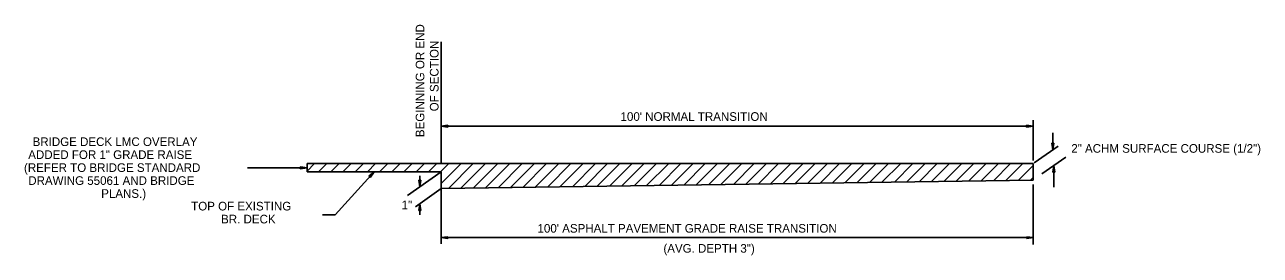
# Model space of a CAD drawing. Extents: x 1931522 to 1935523, y 600380 to 605075.
# Drawn here: x 1931534 to 1932393, y 602766 to 602926 of the extents above; entities that cross this region are included whole.
import ezdxf

# ---------------------------------------------------------------- set-up
doc = ezdxf.new("R2010")
doc.units = 0
doc.layers.add('Default', color=7, linetype='Continuous')
doc.layers.add('R_Border', color=7, linetype='Continuous')

msp = doc.modelspace()

# ---------------------------------------------------------------- linework, layer by layer
at = {"layer": 'Default'}
for p, q in [((1931823.87, 602829.84), (1931823.87, 602914.36)), ((1932235.2, 602831.98), (1932235.2, 602859.98)), ((1931828.54, 602856.49), (1931823.87, 602855.83)), ((1931823.87, 602855.83), (1932235.2, 602855.83)), ((1931828.54, 602855.16), (1931823.87, 602855.83)), ((1931828.54, 602856.27), (1931824.55, 602855.83)), ((1931828.54, 602855.16), (1931824.55, 602855.83)), ((1931828.54, 602856.27), (1931825.44, 602855.83)), ((1931828.54, 602855.38), (1931825.44, 602855.83)), ((1931828.54, 602856.05), (1931826.33, 602855.83)), ((1931828.54, 602855.38), (1931826.33, 602855.83)), ((1931828.54, 602856.05), (1931826.99, 602855.83)), ((1931828.54, 602855.61), (1931826.99, 602855.83)), ((1931828.54, 602855.83), (1931827.88, 602855.83)), ((1931828.54, 602855.61), (1931827.88, 602855.83)), ((1931828.54, 602855.16), (1931828.54, 602856.49)), ((1932230.53, 602856.49), (1932235.2, 602855.83)), ((1932230.53, 602856.49), (1932230.53, 602855.16)), ((1932230.53, 602856.27), (1932233.65, 602855.83)), ((1932230.53, 602856.27), (1932234.3, 602855.83)), ((1932230.53, 602856.05), (1932232.08, 602855.83)), ((1932230.53, 602856.05), (1932232.76, 602855.83)), ((1932230.53, 602855.16), (1932235.2, 602855.83)), ((1932230.53, 602855.61), (1932232.08, 602855.83)), ((1932230.53, 602855.38), (1932233.65, 602855.83)), ((1932230.53, 602855.16), (1932234.3, 602855.83)), ((1932230.53, 602855.38), (1932232.76, 602855.83)), ((1932230.53, 602855.61), (1932231.2, 602855.83)), ((1932230.53, 602855.83), (1932231.2, 602855.83)), ((1932248.96, 602839.41), (1932248.96, 602851.18)), ((1932235.88, 602830.35), (1932252.52, 602841.86)), ((1932248.3, 602844.08), (1932248.96, 602839.41)), ((1932249.63, 602844.08), (1932248.3, 602844.08)), ((1932248.53, 602844.08), (1932248.96, 602840.97)), ((1932248.53, 602844.08), (1932248.96, 602840.31)), ((1932248.74, 602844.08), (1932248.96, 602842.53)), ((1932248.74, 602844.08), (1932248.96, 602841.86)), ((1932249.63, 602844.08), (1932248.96, 602839.41)), ((1932249.18, 602844.08), (1932248.96, 602842.53)), ((1932249.42, 602844.08), (1932248.96, 602840.97)), ((1932249.63, 602844.08), (1932248.96, 602840.31)), ((1932249.42, 602844.08), (1932248.96, 602841.86)), ((1932248.96, 602844.08), (1932248.96, 602843.41)), ((1932249.18, 602844.08), (1932248.96, 602843.41)), ((1932241.31, 602822.65), (1932257.84, 602834.31)), ((1931689.17, 602826.79), (1931730.62, 602826.95)), ((1931725.91, 602826.22), (1931725.96, 602827.63)), ((1931725.91, 602826.22), (1931730.62, 602826.95)), ((1931725.92, 602827.33), (1931729.03, 602826.88)), ((1931725.96, 602827.63), (1931730.62, 602826.95)), ((1931725.96, 602826.53), (1931727.61, 602826.92)), ((1931725.96, 602826.53), (1931728.22, 602826.83)), ((1931726.01, 602826.84), (1931726.8, 602826.89)), ((1931726.01, 602826.84), (1931726.8, 602826.89)), ((1931726.05, 602827.15), (1931727.61, 602826.92)), ((1931726.05, 602827.15), (1931728.22, 602826.83)), ((1931726.09, 602827.46), (1931729.83, 602826.91)), ((1931726.09, 602826.36), (1931729.83, 602826.91)), ((1931726.09, 602826.36), (1931729.03, 602826.88)), ((1931730.62, 602824.06), (1931823.87, 602824.07)), ((1931750.04, 602794.26), (1931777.25, 602824.07)), ((1931773.59, 602821.1), (1931777.25, 602824.07)), ((1931773.78, 602820.86), (1931776.22, 602822.84)), ((1931773.8, 602821.08), (1931776.74, 602823.46)), ((1931774.59, 602820.11), (1931777.25, 602824.07)), ((1931774.61, 602820.33), (1931776.74, 602823.46)), ((1931774.61, 602820.33), (1931776.22, 602822.84)), ((1931800.32, 602807.77), (1931823.87, 602824.07)), ((1931823.87, 602774.21), (1931823.87, 602824.07)), ((1932248.92, 602823.81), (1932249.58, 602828.48)), ((1932248.92, 602823.81), (1932250.25, 602823.81)), ((1932249.14, 602823.81), (1932249.58, 602827.81)), ((1932249.14, 602823.81), (1932249.58, 602826.91)), ((1932249.35, 602823.81), (1932249.58, 602826.25)), ((1932249.35, 602823.81), (1932249.58, 602825.35)), ((1932249.58, 602813.37), (1932249.58, 602828.48)), ((1932250.25, 602823.81), (1932249.58, 602828.48)), ((1932250.25, 602823.81), (1932249.58, 602827.81)), ((1932250.03, 602823.81), (1932249.58, 602826.91)), ((1932250.03, 602823.81), (1932249.58, 602826.25)), ((1932249.8, 602823.81), (1932249.58, 602825.35)), ((1932249.8, 602823.81), (1932249.58, 602824.7)), ((1932249.58, 602823.81), (1932249.58, 602824.7)), ((1931774.59, 602820.11), (1931773.59, 602821.1)), ((1931774.01, 602820.84), (1931775.7, 602822.21)), ((1931774.01, 602820.84), (1931775.23, 602821.83)), ((1931774.21, 602820.6), (1931774.7, 602821.21)), ((1931774.21, 602820.6), (1931774.7, 602821.21)), ((1931774.4, 602820.36), (1931775.7, 602822.21)), ((1931774.4, 602820.36), (1931775.23, 602821.83)), ((1931808.27, 602818.35), (1931808.93, 602813.69)), ((1931809.6, 602818.35), (1931808.27, 602818.35)), ((1931808.49, 602818.35), (1931808.93, 602815.25)), ((1931808.49, 602818.35), (1931808.93, 602814.59)), ((1931808.7, 602818.35), (1931808.93, 602816.81)), ((1931808.7, 602818.35), (1931808.93, 602816.14)), ((1931808.93, 602813.69), (1931808.93, 602821.27)), ((1931809.6, 602818.35), (1931808.93, 602813.69)), ((1931809.15, 602818.35), (1931808.93, 602816.81)), ((1931809.38, 602818.35), (1931808.93, 602815.25)), ((1931809.6, 602818.35), (1931808.93, 602814.59)), ((1931809.38, 602818.35), (1931808.93, 602816.14)), ((1931808.93, 602818.35), (1931808.93, 602817.69)), ((1931809.15, 602818.35), (1931808.93, 602817.69)), ((1932235.2, 602773.59), (1932235.2, 602815.34)), ((1931805.89, 602799.86), (1931823.88, 602812.53)), ((1931808.25, 602797.23), (1931808.91, 602801.9)), ((1931808.25, 602797.23), (1931809.58, 602797.23)), ((1931808.48, 602797.23), (1931808.91, 602801.23)), ((1931808.48, 602797.23), (1931808.91, 602800.34)), ((1931808.68, 602797.23), (1931808.91, 602799.67)), ((1931808.68, 602797.23), (1931808.91, 602798.78)), ((1931809.58, 602797.23), (1931808.91, 602801.9)), ((1931808.91, 602794.35), (1931808.91, 602801.9)), ((1931809.58, 602797.23), (1931808.91, 602801.23)), ((1931809.36, 602797.23), (1931808.91, 602800.34)), ((1931809.36, 602797.23), (1931808.91, 602799.67)), ((1931809.13, 602797.23), (1931808.91, 602798.78)), ((1931809.13, 602797.23), (1931808.91, 602798.13)), ((1931808.91, 602797.23), (1931808.91, 602798.13)), ((1931750.04, 602794.26), (1931741.27, 602794.26)), ((1931828.34, 602779.06), (1931823.87, 602778.41)), ((1932235.2, 602778.41), (1931823.87, 602778.41)), ((1931828.34, 602777.73), (1931823.87, 602778.41)), ((1931828.34, 602779.06), (1931824.55, 602778.41)), ((1931828.34, 602777.96), (1931824.55, 602778.41)), ((1931828.34, 602778.85), (1931825.44, 602778.41)), ((1931828.34, 602777.96), (1931825.44, 602778.41)), ((1931828.34, 602778.85), (1931826.1, 602778.41)), ((1931828.34, 602778.18), (1931826.1, 602778.41)), ((1931828.34, 602778.61), (1931826.99, 602778.41)), ((1931828.34, 602778.18), (1931826.99, 602778.41)), ((1931828.34, 602778.61), (1931827.66, 602778.41)), ((1931828.34, 602778.41), (1931827.66, 602778.41)), ((1931828.34, 602777.73), (1931828.34, 602779.06)), ((1932230.76, 602779.06), (1932235.2, 602778.41)), ((1932230.76, 602779.06), (1932234.53, 602778.41)), ((1932230.76, 602779.06), (1932230.76, 602777.73)), ((1932230.76, 602778.85), (1932233.65, 602778.41)), ((1932230.76, 602778.85), (1932232.99, 602778.41)), ((1932230.76, 602778.61), (1932232.1, 602778.41)), ((1932230.76, 602778.61), (1932231.43, 602778.41)), ((1932230.76, 602777.73), (1932235.2, 602778.41)), ((1932230.76, 602778.18), (1932232.1, 602778.41)), ((1932230.76, 602777.96), (1932233.65, 602778.41)), ((1932230.76, 602777.96), (1932234.53, 602778.41)), ((1932230.76, 602778.18), (1932232.99, 602778.41)), ((1932230.76, 602778.41), (1932231.43, 602778.41))]:
    msp.add_line(p, q, dxfattribs=at)
msp.add_lwpolyline([(1931823.87, 602824.07), (1931823.87, 602824.07)], dxfattribs=at)
at = {"layer": 'R_Border'}
for p, q in [((1931810.01, 602829.84), (1931730.62, 602829.83)), ((1931730.62, 602829.83), (1931730.62, 602824.06)), ((1931730.62, 602824.61), (1931735.85, 602829.83)), ((1931738.56, 602824.06), (1931744.33, 602829.83)), ((1931747.05, 602824.06), (1931752.82, 602829.83)), ((1931755.54, 602824.06), (1931761.31, 602829.83)), ((1931764.02, 602824.07), (1931769.79, 602829.84)), ((1931772.51, 602824.07), (1931778.28, 602829.84)), ((1931780.99, 602824.07), (1931786.76, 602829.84)), ((1931789.48, 602824.07), (1931795.25, 602829.84)), ((1931797.97, 602824.07), (1931803.74, 602829.84)), ((1931806.45, 602824.07), (1931812.22, 602829.84)), ((1931823.87, 602829.84), (1931810.01, 602829.84)), ((1931814.94, 602824.07), (1931820.7, 602829.84)), ((1931823.42, 602824.07), (1931829.19, 602829.84)), ((1932235.2, 602829.88), (1931823.87, 602829.84)), ((1932235.2, 602829.88), (1931823.87, 602829.84)), ((1931823.87, 602824.07), (1931823.87, 602812.53)), ((1931823.87, 602824.07), (1931823.87, 602818.3)), ((1931823.88, 602816.04), (1931837.68, 602829.84)), ((1931828.92, 602812.6), (1931846.16, 602829.84)), ((1931837.53, 602812.72), (1931854.65, 602829.84)), ((1931846.13, 602812.84), (1931863.13, 602829.84)), ((1931854.74, 602812.96), (1931871.62, 602829.84)), ((1931863.35, 602813.08), (1931880.11, 602829.84)), ((1931871.96, 602813.21), (1931888.59, 602829.84)), ((1931880.56, 602813.33), (1931897.08, 602829.84)), ((1931889.17, 602813.45), (1931905.56, 602829.84)), ((1931897.78, 602813.57), (1931914.05, 602829.84)), ((1931906.38, 602813.69), (1931922.54, 602829.85)), ((1931914.99, 602813.81), (1931931.02, 602829.85)), ((1931923.6, 602813.93), (1931939.51, 602829.85)), ((1931932.2, 602814.06), (1931948, 602829.85)), ((1931940.81, 602814.18), (1931956.48, 602829.85)), ((1931949.42, 602814.3), (1931964.97, 602829.85)), ((1931958.02, 602814.42), (1931973.45, 602829.85)), ((1931966.63, 602814.54), (1931981.94, 602829.85)), ((1931975.24, 602814.66), (1931990.43, 602829.85)), ((1931983.84, 602814.79), (1931998.91, 602829.85)), ((1931992.45, 602814.91), (1932007.4, 602829.85)), ((1932001.06, 602815.03), (1932015.88, 602829.85)), ((1932009.67, 602815.15), (1932024.37, 602829.86)), ((1932018.27, 602815.27), (1932032.86, 602829.86)), ((1932026.88, 602815.39), (1932041.34, 602829.86)), ((1932035.49, 602815.51), (1932049.83, 602829.86)), ((1932044.09, 602815.64), (1932058.32, 602829.86)), ((1932052.7, 602815.76), (1932066.8, 602829.86)), ((1932061.31, 602815.88), (1932075.29, 602829.86)), ((1932069.91, 602816), (1932083.77, 602829.86)), ((1932078.52, 602816.12), (1932092.26, 602829.86)), ((1932087.13, 602816.24), (1932100.75, 602829.86)), ((1932095.73, 602816.37), (1932109.23, 602829.86)), ((1932104.34, 602816.49), (1932117.72, 602829.87)), ((1932112.95, 602816.61), (1932126.2, 602829.87)), ((1932121.55, 602816.73), (1932134.69, 602829.87)), ((1932130.16, 602816.85), (1932143.18, 602829.87)), ((1932138.77, 602816.97), (1932151.66, 602829.87)), ((1932147.37, 602817.1), (1932160.15, 602829.87)), ((1932155.98, 602817.22), (1932168.63, 602829.87)), ((1932164.59, 602817.34), (1932177.12, 602829.87)), ((1932173.2, 602817.46), (1932185.61, 602829.87)), ((1932181.8, 602817.58), (1932194.09, 602829.87)), ((1932190.41, 602817.7), (1932202.58, 602829.87)), ((1932199.02, 602817.82), (1932211.07, 602829.87)), ((1932207.62, 602817.95), (1932219.55, 602829.88)), ((1932216.23, 602818.07), (1932228.04, 602829.88)), ((1932224.84, 602818.19), (1932235.2, 602828.56)), ((1932235.22, 602818.34), (1932235.2, 602829.88)), ((1932235.22, 602818.34), (1932235.2, 602829.88)), ((1932235.22, 602818.34), (1932235.2, 602829.88)), ((1931823.87, 602812.53), (1932235.22, 602818.34)), ((1931823.87, 602812.53), (1932235.22, 602818.34)), ((1932233.44, 602818.31), (1932235.21, 602820.08))]:
    msp.add_line(p, q, dxfattribs=at)
msp.add_lwpolyline([(1931730.62, 602824.06), (1931823.87, 602824.07)], dxfattribs=at)

# ---------------------------------------------------------------- texts
at = {"layer": 'Default'}
for s, rotation, p in [('BEGINNING OR END', 90, (1931812.14, 602848.22)), ('OF SECTION', 90, (1931822, 602866.17)), ("100' NORMAL TRANSITION ", 360, (1931948.48, 602859.52)), ('BRIDGE DECK LMC OVERLAY ', 360, (1931539.88, 602842.04)), ('ADDED FOR 1" GRADE RAISE', 360, (1931536.85, 602833.04)), ('(REFER TO BRIDGE STANDARD', 360, (1931533.9, 602824.04)), ('DRAWING 55061 AND BRIDGE', 360, (1931536.86, 602815.04)), (' PLANS.)', 360, (1931585.33, 602806.04)), ('TOP OF EXISTING ', 360, (1931650.08, 602797.29)), ('1"', 360, (1931796.33, 602798.13)), ('BR. DECK', 360, (1931670.87, 602788.29)), ("100' ASPHALT PAVEMENT GRADE RAISE TRANSITION", 360, (1931890.78, 602781.87)), ('(AVG. DEPTH 3")', 360, (1931978.27, 602767.96))]:
    msp.add_text(s, height=6, rotation=rotation, dxfattribs=at).set_placement(p)
msp.add_text('2" ACHM SURFACE COURSE (1/2")', height=6, dxfattribs=at).set_placement((1932261.73, 602837.38))

doc.saveas('drawing.dxf')
